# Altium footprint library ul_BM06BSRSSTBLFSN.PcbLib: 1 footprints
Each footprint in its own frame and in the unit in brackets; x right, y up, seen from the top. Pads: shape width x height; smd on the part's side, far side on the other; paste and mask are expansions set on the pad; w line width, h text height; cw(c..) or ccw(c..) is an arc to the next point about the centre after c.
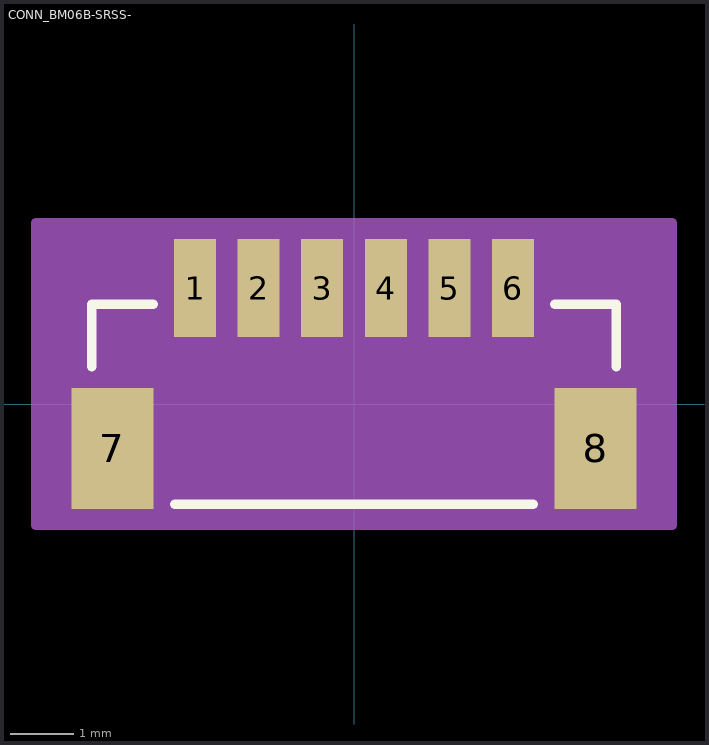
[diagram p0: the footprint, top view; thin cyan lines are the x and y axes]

## CONN_BM06B-SRSS- [mil]
pads (8):
  rect 26x61 smd paste+0 mask+0: 1(-98.43,72.04) 2(-59.06,72.04) 3(-19.68,72.04) 4(19.68,72.04) 5(59.06,72.04) 6(98.43,72.04)
  rect 51x75 smd: 7(-149.61,-27.37) 8(149.61,-27.37)
Top Overlay:
  lines w6: -162.5,23.23 -162.5,62 -124.53,62 ; -111.01,-62 111.01,-62 ; 124.53,62 162.5,62 162.5,23.23
Mechanical 5:
  region: -172.5,72 172.5,72 172.5,-72 -172.5,-72
Mechanical 13:
  lines w1: -157.5,-57 -157.5,57 157.5,57 157.5,-57 -157.5,-57
Mechanical 15:
  region: 197.11,112.54 -197.11,112.54 -197.11,-75 197.11,-75
  lines w6: -197.11,-75 197.11,-75 197.11,112.54 -197.11,112.54 -197.11,-75
3D body: height 10, standoff 0, extent 0,0 10,10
